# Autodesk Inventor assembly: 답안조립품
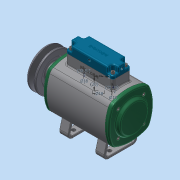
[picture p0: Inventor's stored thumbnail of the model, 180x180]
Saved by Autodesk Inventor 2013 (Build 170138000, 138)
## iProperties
Created: 2016-10
Part Number: 답안조립품
Document SubType Name: Assembly
Designer: user
Author: user
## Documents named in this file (18)
- C:\Users\user\Desktop\361008V1005\답안조립품.iam
- C:\Users\user\Desktop\361008V1005\본체.ipt
- C:\Users\user\Desktop\361008V1005\베어링 6203.ipt
- C:\Users\user\Desktop\361008V1005\앞커버.ipt
- C:\Users\user\Desktop\361008V1005\축.ipt
- C:\Users\user\Desktop\361008V1005\키 - 5 x 5 x 18.ipt
- C:\Users\user\Desktop\361008V1005\오일실 17 30 8.ipt
- C:\Users\user\Desktop\361008V1005\부시.ipt
- C:\Users\user\Desktop\361008V1005\슬라이드.ipt
- C:\Users\user\Desktop\361008V1005\스프링1.ipt
- C:\Users\user\Desktop\361008V1005\스프링2.ipt
- C:\Users\user\Desktop\361008V1005\스프링3.ipt
- C:\Users\user\Desktop\361008V1005\뒷커버.ipt
- C:\Users\user\Desktop\361008V1005\헤더커버.ipt
- C:\Users\user\Desktop\361008V1005\V-벨트풀리.ipt
- C:\Users\user\Desktop\361008V1005\멈춤나사 M4x5.ipt
- C:\Users\user\Desktop\361008V1005\볼트 M4 x 12.ipt
- C:\Users\user\Desktop\361008V1005\볼트 M4 x 16.ipt
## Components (4 placed, 3 different names)
1. 7-베어링 6203:1
2. 7-베어링 6203:2
3. 헤더커버:1
4. V-벨트풀리:1
